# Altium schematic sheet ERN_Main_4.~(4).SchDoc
size A; SheetNumber: 4; SheetTotal: 4; SPICEModelCacheELVNKBHK: <root> / <DocumentId>ELVNKBHK</DocumentId> / <CacheFrame Number="0"> / <Model Name="led2" Kind="MDL"> / <Text>*Typ RED,GREEN,YELLOW,AMBER GaAs LED: Vf=2.1V Vr=4V If=40mA trr=3uS / *LED Pinout: 1=A, 2=K / .MODEL LED2 D (IS=93.1P RS=42M N=4.61 BV=4 IBV=10U / + CJO=2.97P VJ=.75 M=.333 TT=4.32U)</Text> / </Model> / </CacheFrame> / </root>
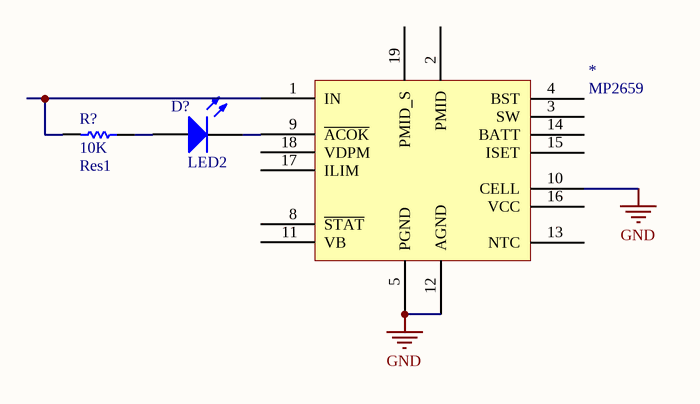
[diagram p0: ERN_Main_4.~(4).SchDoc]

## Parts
*  MP2659
D?  LED2  [3.2X1.6X1.1]
R?  Res1  value 10K  [AXIAL-0.3]

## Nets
GND: *.5(PGND) *.10(CELL) *.12(AGND)
Net*_1: *.1(IN) R?.2
Net*_9: *.9(~{ACOK}) D?.2(K)
NetD?_1: D?.1(A) R?.1

Not connected (* = marked no-connect by the designer): * 2(PMID) 3(SW) 4(BST) 8(~{STAT}) 11(VB) 13(NTC) 14(BATT) 15(ISET) 16(VCC) 17(ILIM) 18(VDPM) 19(PMID_S)

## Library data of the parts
* = MP2659: 3S-6S Standalone Switching Charger
D? = LED2: Typical RED, GREEN, YELLOW, AMBER GaAs LED
R? = Res1: Resistor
